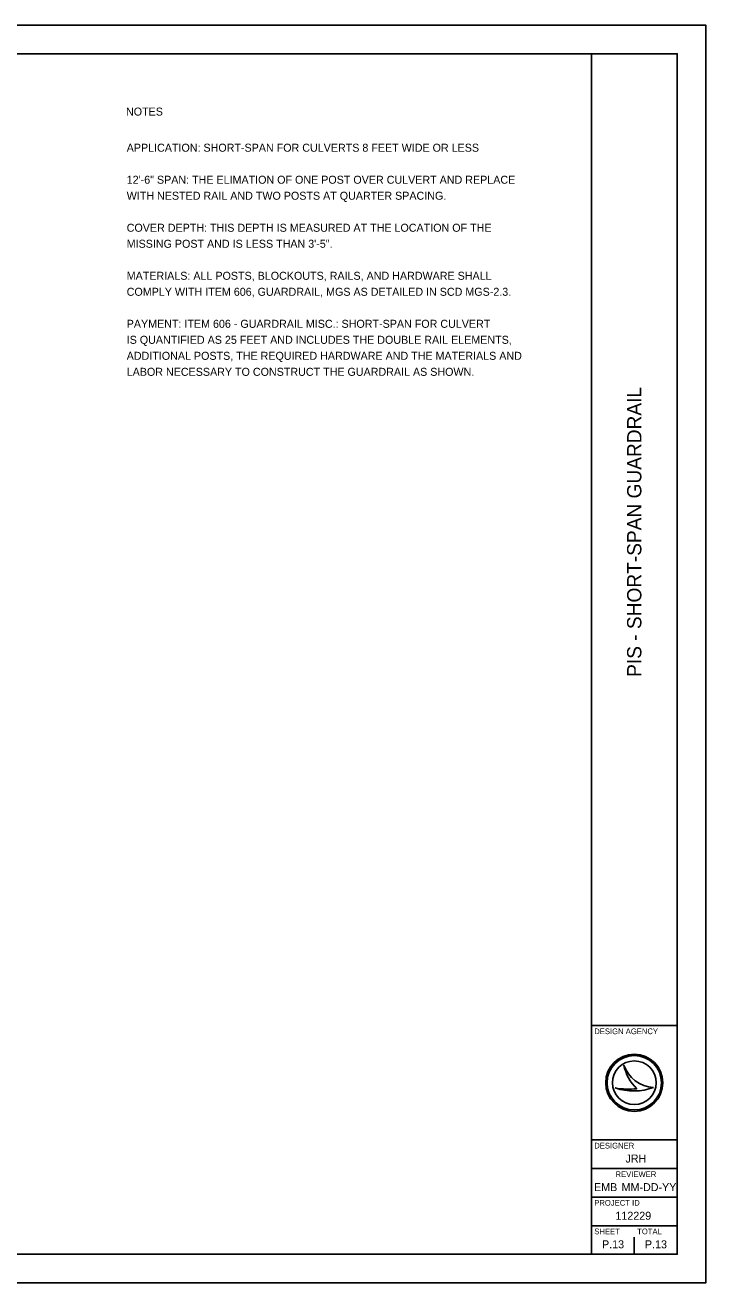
# Model space of a CAD drawing. Extents: x 0 to 170, y 0 to 110.
# Drawn here: x 110.5 to 170, y 0 to 110 of the extents above; entities that cross this region are included whole.
import ezdxf

# ---------------------------------------------------------------- set-up
doc = ezdxf.new("R2010")
doc.units = 0
for name, color, linetype in [('BR_P_Rail_Stl_Det', 7, 'Continuous'), ('SH_Border', 7, 'Continuous'), ('SH_Cut_Line', 7, 'Continuous'), ('SH_Data', 7, 'Continuous')]:
    doc.layers.add(name, color=color, linetype=linetype)

msp = doc.modelspace()

# ---------------------------------------------------------------- linework, layer by layer
at = {"layer": 'SH_Border'}
for p, q in [((160, 2.5), (160, 107.5)), ((160, 22.5), (167.5, 22.5)), ((160, 12.5), (167.5, 12.5)), ((160, 10), (167.5, 10)), ((160, 7.5), (167.5, 7.5)), ((160, 5), (167.5, 5))]:
    msp.add_line(p, q, dxfattribs=at)
msp.add_lwpolyline([(7.5, 107.5), (167.5, 107.5), (167.5, 2.5), (7.5, 2.5)], close=True, dxfattribs=at)
at = {"layer": 'SH_Cut_Line'}
msp.add_lwpolyline([(0, 0), (170, 0), (170, 110), (0, 110)], close=True, dxfattribs=at)
at = {"layer": 'SH_Data'}
for p, q in [((162.84, 19.05), (162.84, 19.05)), ((162.09, 17.05), (162.09, 17.05)), ((163.75, 17.5), (163.75, 17.5)), ((165.44, 17.09), (165.44, 17.09)), ((161.87, 3.38), (161.87, 3.38)), ((163.75, 2.5), (163.75, 4))]:
    msp.add_line(p, q, dxfattribs=at)
for radius in [2.5, 2.38, 2.38, 1.91]:
    msp.add_circle((163.75, 17.5), radius, dxfattribs=at)
for centre, radius, start, end in [((165.58, 19.99), 2.9, 198.9257, 198.9319), ((166.73, 19.85), 3.98, 191.6379, 191.6421), ((165.58, 19.99), 2.9, 198.9319, 267.1657), ((166.73, 19.85), 3.98, 191.6421, 226.0947), ((163.7, 21.85), 5.07, 251.4576, 290.0832), ((163.24, 23.27), 6.33, 259.4964, 259.4995), ((163.7, 21.85), 5.07, 251.4527, 251.4576), ((163.24, 23.27), 6.33, 259.4995, 276.6672)]:
    msp.add_arc(centre, radius, start, end, dxfattribs=at)

# ---------------------------------------------------------------- texts
at = {"layer": 'BR_P_Rail_Stl_Det'}
for s, p in [('NOTES', (119.33, 102.09)), ('APPLICATION: SHORT-SPAN FOR CULVERTS 8 FEET WIDE OR LESS', (119.39, 98.93)), ('12\'-6" SPAN: THE ELIMATION OF ONE POST OVER CULVERT AND REPLACE ', (119.39, 96.13)), ('WITH NESTED RAIL AND TWO POSTS AT QUARTER SPACING.', (119.39, 94.73)), ('COVER DEPTH: THIS DEPTH IS MEASURED AT THE LOCATION OF THE ', (119.39, 91.93)), ('MISSING POST AND IS LESS THAN 3\'-5".', (119.39, 90.53)), ('MATERIALS: ALL POSTS, BLOCKOUTS, RAILS, AND HARDWARE SHALL ', (119.39, 87.73)), ('COMPLY WITH ITEM 606, GUARDRAIL, MGS AS DETAILED IN SCD MGS-2.3.', (119.39, 86.33)), ('PAYMENT: ITEM 606 - GUARDRAIL MISC.: SHORT-SPAN FOR CULVERT', (119.39, 83.53)), ('IS QUANTIFIED AS 25 FEET AND INCLUDES THE DOUBLE RAIL ELEMENTS, ', (119.39, 82.13)), ('ADDITIONAL POSTS, THE REQUIRED HARDWARE AND THE MATERIALS AND', (119.39, 80.73)), ('LABOR NECESSARY TO CONSTRUCT THE GUARDRAIL AS SHOWN.', (119.39, 79.33))]:
    msp.add_text(s, height=0.7, dxfattribs=at).set_placement(p)
at = {"layer": 'SH_Data'}
msp.add_text('PIS - SHORT-SPAN GUARDRAIL', height=1.25, rotation=90, dxfattribs=at).set_placement((164.37, 53))
for s, height, p in [('DESIGN AGENCY', 0.5, (160.25, 21.75)), ('DESIGNER', 0.5, (160.25, 11.75)), ('JRH', 0.7, (162.98, 10.52)), ('REVIEWER', 0.5, (162.11, 9.25)), ('EMB', 0.7, (160.23, 8.02)), ('MM-DD-YY', 0.7, (162.64, 8.02)), ('PROJECT ID', 0.5, (160.25, 6.75)), ('112229', 0.7, (162.1, 5.52)), ('SHEET', 0.5, (160.25, 4.25)), ('TOTAL', 0.5, (164, 4.25)), ('P.13', 0.7, (160.93, 3.02)), ('P.13', 0.7, (164.68, 3.02))]:
    msp.add_text(s, height=height, dxfattribs=at).set_placement(p)

doc.saveas('drawing.dxf')
